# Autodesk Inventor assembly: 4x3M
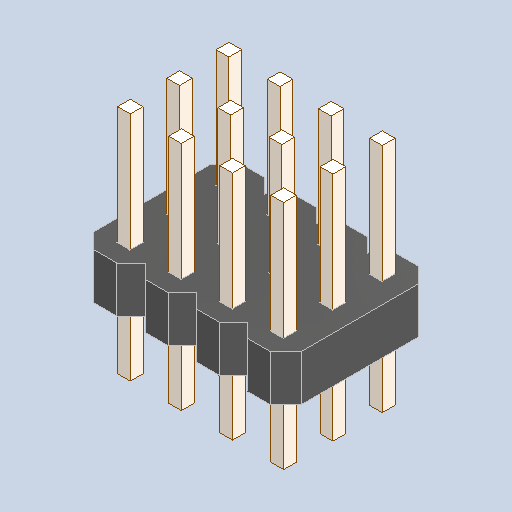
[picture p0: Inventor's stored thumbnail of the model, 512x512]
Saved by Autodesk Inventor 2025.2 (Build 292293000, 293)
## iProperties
Created: 2025-04
Part Number: 4x3M
Description: PART--DESC
Document SubType Name: Assembly
Designer: BennF
Author: BennF
Revision Number: NONE
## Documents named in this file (3)
- C:\Users\BennF\Nextcloud\Benutzer\CNC JarBeRi\existing parts\Electronics\RepRap A4988 Shied (USE WITHOUT ARDUINO)\reprap-a4988-1.snapshot.1\RepRap\RepRap\4x3M.iam
- C:\Users\BennF\Nextcloud\Benutzer\CNC JarBeRi\existing parts\Electronics\RepRap A4988 Shied (USE WITHOUT ARDUINO)\reprap-a4988-1.snapshot.1\RepRap\RepRap\4x3M Geometry.ipt
- C:\Users\BennF\Nextcloud\Benutzer\CNC JarBeRi\existing parts\Electronics\RepRap A4988 Shied (USE WITHOUT ARDUINO)\reprap-a4988-1.snapshot.1\RepRap\RepRap\Pin7.ipt
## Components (2 placed, 2 different names)
1. 4x3M Geometry
2. Pin7
